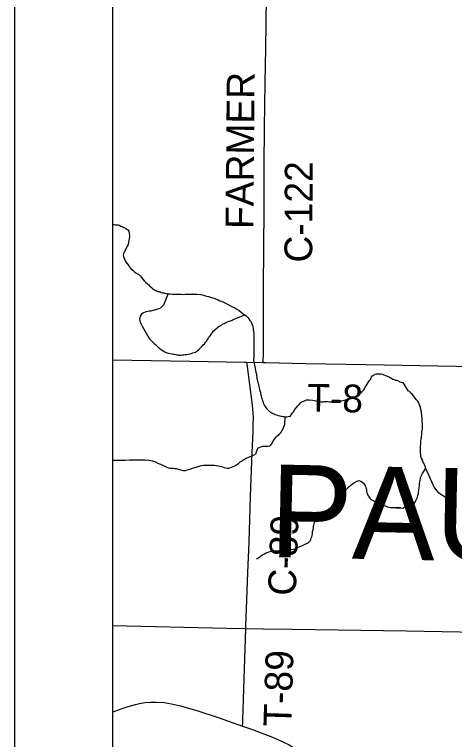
# Model space of a CAD drawing. Extents: x 2.1 to 73.9, y 4 to 26.
# Drawn here: x 41.859 to 42.308, y 21.52 to 22.261 of the extents above; entities that cross this region are included whole.
import ezdxf

# ---------------------------------------------------------------- set-up
doc = ezdxf.new("R2010")
doc.units = 0
for name, color, linetype in [('GM_X_County_Road', 7, 'Continuous'), ('GM_X_County_Road_Text', 7, 'Continuous'), ('GM_X_County_Text', 7, 'Continuous'), ('GM_X_Minor_River', 7, 'Continuous'), ('GM_X_Township_Road', 7, 'Continuous'), ('GM_X_Township_Road_Text', 7, 'Continuous'), ('SH_Data', 7, 'Continuous')]:
    doc.layers.add(name, color=color, linetype=linetype)

msp = doc.modelspace()

# ---------------------------------------------------------------- linework, layer by layer
at = {"layer": 'GM_X_County_Road'}
for points in [[(42.11267, 21.90506), (42.11274, 21.91552), (42.11287, 21.92921), (42.11306, 21.99168), (42.11314, 22.01188), (42.11339, 22.03675), (42.11342, 22.04701), (42.11352, 22.06939), (42.11355, 22.08244), (42.11375, 22.10636), (42.11409, 22.1449), (42.11475, 22.19121), (42.11514, 22.22634), (42.1155, 22.2512), (42.11674, 22.33884), (42.11734, 22.38514), (42.11768, 22.40528)], [(42.09471, 21.63337), (42.09482, 21.63621), (42.09551, 21.65327), (42.09685, 21.69051), (42.0981, 21.72152), (42.0997, 21.76807), (42.10129, 21.81306), (42.10221, 21.83477), (42.10241, 21.84252), (42.10252, 21.84872), (42.10243, 21.85337), (42.10214, 21.85781), (42.10127, 21.86417), (42.09652, 21.90111), (42.09598, 21.90535)], [(41.95853, 21.63624), (42.07549, 21.63377), (42.09471, 21.63337)], [(42.09471, 21.63337), (42.1128, 21.63298), (42.14235, 21.63277), (42.25895, 21.63095), (42.31336, 21.62998), (42.38021, 21.62891), (42.48593, 21.62681), (42.52323, 21.62609), (42.54808, 21.62566), (42.56206, 21.62541), (42.57761, 21.62528), (42.59159, 21.62515), (42.60148, 21.62491)]]:
    msp.add_lwpolyline(points, dxfattribs=at)
at = {"layer": 'GM_X_Minor_River'}
for points in [[(41.95853, 22.04616), (41.96031, 22.0461), (41.96182, 22.04586), (41.96315, 22.04582), (41.96429, 22.04579), (41.96542, 22.04537), (41.96729, 22.04455), (41.9686, 22.04394), (41.97029, 22.04313), (41.97179, 22.04251), (41.97328, 22.04152), (41.97421, 22.04073), (41.97531, 22.03936), (41.97565, 22.03821), (41.97579, 22.03669), (41.97594, 22.03536), (41.97589, 22.03365), (41.97583, 22.03175), (41.97539, 22.02986), (41.97495, 22.02798), (41.9745, 22.02571), (41.97349, 22.02384), (41.97266, 22.02159), (41.97126, 22.01936), (41.97064, 22.01767), (41.97002, 22.01617), (41.96959, 22.01466), (41.96974, 22.01333), (41.97133, 22.00967), (41.97206, 22.0085), (41.97333, 22.00675), (41.97461, 22.005), (41.9757, 22.00326), (41.97754, 22.0013), (41.97938, 21.99935), (41.98123, 21.99777), (41.9829, 21.99639), (41.98459, 21.99577), (41.98552, 21.99498), (41.98644, 21.99419), (41.98736, 21.99321), (41.98827, 21.99185), (41.98955, 21.99029), (41.99102, 21.98854), (41.99268, 21.98696), (41.99417, 21.98578), (41.99564, 21.9844), (41.99693, 21.98303), (41.9986, 21.98165), (41.99989, 21.98047), (42.00138, 21.97947), (42.0027, 21.97886), (42.00382, 21.97845), (42.00494, 21.97784), (42.00627, 21.97761), (42.00721, 21.9772), (42.00833, 21.97679), (42.00965, 21.97637), (42.01117, 21.97632), (42.01305, 21.97569), (42.01609, 21.97541), (42.01798, 21.97516), (42.01987, 21.97491), (42.02178, 21.97504), (42.02406, 21.97497), (42.02653, 21.97489), (42.02881, 21.97482), (42.0309, 21.97475), (42.03318, 21.97487), (42.03546, 21.9748), (42.03794, 21.97491), (42.04079, 21.97501), (42.04231, 21.97496), (42.04346, 21.97512), (42.04479, 21.97508), (42.04896, 21.97457), (42.05065, 21.97413), (42.05273, 21.97369), (42.0548, 21.97305), (42.05688, 21.97242), (42.05876, 21.97179), (42.06064, 21.97116), (42.06234, 21.97073), (42.0644, 21.9699), (42.06666, 21.96907), (42.06815, 21.96827), (42.06985, 21.96764), (42.07135, 21.96703), (42.07266, 21.96642), (42.07397, 21.96581), (42.07547, 21.965), (42.07678, 21.96439), (42.07902, 21.96318), (42.08127, 21.96216), (42.08352, 21.96114), (42.08576, 21.95955), (42.08799, 21.95815), (42.09022, 21.95656), (42.09227, 21.95498), (42.09394, 21.95378)], [(42.01538, 21.97547), (42.01058, 21.96361), (42.0098, 21.96269), (42.00863, 21.96177), (42.00764, 21.96066), (42.00591, 21.95996), (42.00457, 21.95962), (42.00264, 21.95892), (42.00149, 21.95858), (41.99996, 21.95825), (41.99881, 21.95809), (41.99785, 21.95774), (41.99614, 21.95761), (41.99441, 21.95709), (41.99269, 21.95676), (41.9898, 21.95571), (41.98824, 21.95443), (41.98745, 21.95351), (41.98685, 21.95258), (41.98642, 21.95088), (41.98638, 21.94974), (41.98653, 21.94841), (41.98668, 21.94726), (41.98722, 21.94611), (41.98792, 21.94438), (41.989, 21.94225), (41.99025, 21.93975), (41.9917, 21.93742), (41.99315, 21.9351), (41.9944, 21.93259), (41.99567, 21.93046), (41.99676, 21.9289), (41.99805, 21.92753), (41.99934, 21.92635), (42.00119, 21.92459), (42.00248, 21.92341), (42.00377, 21.92204), (42.00525, 21.92066), (42.00711, 21.91946), (42.00859, 21.91809), (42.01026, 21.91689), (42.01194, 21.91589), (42.01344, 21.91528), (42.01457, 21.91486), (42.0159, 21.91463), (42.01759, 21.9142), (42.01968, 21.91394), (42.021, 21.91371), (42.02214, 21.91348), (42.02327, 21.91326), (42.0244, 21.91303), (42.02573, 21.9128), (42.02687, 21.91277), (42.02839, 21.91272), (42.02991, 21.91286), (42.03144, 21.913), (42.03296, 21.91315), (42.03468, 21.91347), (42.03622, 21.9138), (42.03775, 21.91414), (42.03889, 21.91429), (42.04063, 21.915), (42.04332, 21.91586), (42.04506, 21.91695), (42.04662, 21.91823), (42.0476, 21.91896), (42.04897, 21.92043), (42.04976, 21.92136), (42.05134, 21.92302), (42.05252, 21.92431), (42.05371, 21.92598), (42.0547, 21.92709), (42.0553, 21.92802), (42.05609, 21.92914), (42.05669, 21.93007), (42.05789, 21.93193), (42.05868, 21.93285), (42.05928, 21.93378), (42.05988, 21.93472), (42.06067, 21.93564), (42.06187, 21.9375), (42.06323, 21.93841), (42.06402, 21.93934), (42.06519, 21.94025), (42.06635, 21.94116), (42.06733, 21.94189), (42.06849, 21.94261), (42.06985, 21.94333), (42.07102, 21.94425), (42.07275, 21.94514), (42.07449, 21.94584), (42.07603, 21.94656), (42.07795, 21.94726), (42.07911, 21.94779), (42.08007, 21.94814), (42.08104, 21.94849), (42.082, 21.94903), (42.08296, 21.94938), (42.09394, 21.95378)], [(42.09394, 21.95378), (42.09561, 21.9524), (42.0969, 21.95122), (42.098, 21.94986), (42.0989, 21.94812), (42.10018, 21.94656), (42.10088, 21.94464), (42.10159, 21.94291), (42.10212, 21.94156), (42.10226, 21.94004), (42.1024, 21.93851), (42.10273, 21.93679), (42.10287, 21.93527), (42.10301, 21.93356), (42.10295, 21.93166), (42.10287, 21.92938), (42.10317, 21.92671), (42.10308, 21.92368), (42.10298, 21.92045), (42.10287, 21.91703), (42.10295, 21.91361), (42.10286, 21.91058), (42.10257, 21.90755), (42.10399, 21.90054)], [(42.10399, 21.90054), (42.105, 21.89511), (42.10568, 21.89318), (42.10582, 21.89185), (42.10594, 21.89013), (42.10626, 21.8886), (42.1066, 21.88763), (42.10693, 21.88629), (42.10726, 21.88514), (42.10758, 21.88361), (42.10791, 21.88226), (42.10823, 21.88092), (42.10886, 21.87748), (42.1092, 21.87651), (42.10935, 21.87555), (42.10969, 21.87459), (42.10984, 21.87345), (42.11017, 21.87229), (42.11051, 21.87133), (42.11067, 21.87037), (42.11116, 21.86845), (42.11168, 21.8671), (42.11219, 21.86556), (42.11269, 21.86383), (42.11321, 21.86267), (42.11374, 21.8617), (42.11463, 21.86014), (42.11535, 21.85898), (42.11607, 21.858), (42.11735, 21.8568), (42.11827, 21.85582), (42.11919, 21.85521), (42.1203, 21.8544), (42.12142, 21.85379), (42.12254, 21.85318), (42.12366, 21.85275), (42.12459, 21.85214), (42.12609, 21.8517), (42.12797, 21.85106), (42.12967, 21.85061), (42.1308, 21.85037), (42.13174, 21.85014), (42.13307, 21.8499), (42.13401, 21.84986), (42.13534, 21.84962), (42.13667, 21.84975), (42.1382, 21.84988), (42.13936, 21.85021), (42.14032, 21.85037), (42.14133, 21.85185), (42.14254, 21.8537), (42.14374, 21.85517), (42.14456, 21.85665), (42.14797, 21.86089), (42.14957, 21.86272), (42.15057, 21.86401), (42.15154, 21.86454), (42.15271, 21.86525), (42.15368, 21.86578), (42.15465, 21.86612), (42.156, 21.86664), (42.15697, 21.86698), (42.15792, 21.86694), (42.15963, 21.86687), (42.16323, 21.86654), (42.16493, 21.86628), (42.16626, 21.86603), (42.16815, 21.86577), (42.16948, 21.86571), (42.17041, 21.8653), (42.17193, 21.86505), (42.17288, 21.86501), (42.17402, 21.86496), (42.17497, 21.86511), (42.17612, 21.86526), (42.17727, 21.8654), (42.1786, 21.86535), (42.18049, 21.86508), (42.1822, 21.86501), (42.18467, 21.86491), (42.1883, 21.86514), (42.1904, 21.86544), (42.19175, 21.86576), (42.19271, 21.8661), (42.19406, 21.86643), (42.1954, 21.86676), (42.19656, 21.86709), (42.19771, 21.86742), (42.19868, 21.86776), (42.20021, 21.86808), (42.20176, 21.86878), (42.20658, 21.87029), (42.20755, 21.87063), (42.20929, 21.87132), (42.21026, 21.87185), (42.21144, 21.87276), (42.21244, 21.87386), (42.21364, 21.87533)], [(42.21364, 21.87533), (42.21543, 21.87734), (42.21604, 21.87827), (42.21686, 21.87976), (42.21769, 21.88143), (42.21871, 21.8831), (42.21973, 21.88477), (42.22093, 21.88624), (42.22213, 21.88771), (42.22255, 21.88864), (42.22318, 21.89014), (42.22437, 21.89142), (42.22555, 21.89232), (42.22653, 21.89304), (42.22788, 21.89356), (42.22922, 21.89369), (42.23017, 21.89366), (42.23207, 21.89358), (42.23302, 21.89354), (42.23452, 21.8931), (42.23583, 21.89248), (42.23752, 21.89184), (42.23883, 21.89141), (42.23995, 21.89079), (42.24127, 21.89036), (42.2422, 21.88994), (42.24387, 21.88892), (42.24498, 21.88812), (42.24649, 21.88768), (42.2478, 21.88724), (42.24874, 21.88702), (42.24987, 21.88659), (42.25229, 21.88535), (42.25361, 21.88492), (42.25436, 21.8847), (42.25575, 21.8846)], [(42.27405, 21.80745), (42.27324, 21.81348), (42.27332, 21.81614), (42.27342, 21.81975), (42.27367, 21.82183), (42.27372, 21.82354), (42.27377, 21.82506), (42.274, 21.82658), (42.27424, 21.82828), (42.27447, 21.82979), (42.27451, 21.83112), (42.27475, 21.83264), (42.27479, 21.83416), (42.27503, 21.83586), (42.27526, 21.83718), (42.27531, 21.8387), (42.27534, 21.84003), (42.27537, 21.84098), (42.27521, 21.84213), (42.2751, 21.84479), (42.27514, 21.84612), (42.27483, 21.8486), (42.27469, 21.85032), (42.27455, 21.85203), (42.2744, 21.85337), (42.27424, 21.85432), (42.27408, 21.85547), (42.27392, 21.85642), (42.27376, 21.85738), (42.27341, 21.85834), (42.27325, 21.85967), (42.27272, 21.86102), (42.27218, 21.86199), (42.27183, 21.86295), (42.2713, 21.86448), (42.27058, 21.86564), (42.26909, 21.86702), (42.268, 21.86876), (42.26727, 21.86973), (42.26616, 21.87091), (42.26469, 21.87266), (42.26322, 21.87422), (42.2623, 21.87539), (42.26118, 21.87599), (42.26025, 21.87678), (42.25575, 21.8846)], [(42.13476, 21.84959), (42.13444, 21.84148), (42.13235, 21.83682), (42.13173, 21.83552), (42.13091, 21.83422), (42.12991, 21.83293), (42.12853, 21.83166), (42.12772, 21.83055), (42.12654, 21.82965), (42.12495, 21.828), (42.12376, 21.82672), (42.12315, 21.82579), (42.12254, 21.82468), (42.12212, 21.82375), (42.12151, 21.82282), (42.1201, 21.82079), (42.11891, 21.8197), (42.11719, 21.81939), (42.11528, 21.81927), (42.11319, 21.81936), (42.11204, 21.81921), (42.11108, 21.81906), (42.10993, 21.81873), (42.10819, 21.81804), (42.10664, 21.81734), (42.10466, 21.81151)], [(42.02822, 21.79546), (42.02936, 21.79505), (42.03069, 21.79483), (42.03163, 21.79462), (42.03335, 21.79477), (42.03489, 21.79531), (42.03796, 21.79619), (42.04045, 21.79708), (42.04314, 21.79797), (42.04506, 21.7985), (42.04602, 21.79886), (42.04717, 21.79921), (42.04813, 21.79957), (42.04966, 21.79973), (42.05176, 21.80006), (42.05367, 21.8002), (42.05501, 21.80017), (42.05672, 21.80013), (42.05787, 21.8003), (42.05901, 21.80027), (42.06091, 21.80023), (42.06301, 21.80018), (42.06472, 21.79995), (42.06642, 21.79953), (42.06813, 21.7993), (42.06984, 21.79888), (42.07097, 21.79848), (42.07267, 21.79768), (42.07571, 21.79723), (42.07723, 21.7972), (42.07857, 21.79754), (42.08011, 21.79808), (42.08203, 21.7988), (42.08376, 21.79952), (42.08569, 21.8008), (42.08744, 21.80209), (42.08919, 21.80358), (42.09092, 21.8043), (42.09189, 21.80523), (42.09305, 21.80596), (42.09421, 21.80669), (42.09537, 21.80724), (42.10466, 21.81151)], [(41.95853, 21.80517), (41.95985, 21.80519), (41.96385, 21.80529), (41.96786, 21.80539), (41.97167, 21.8055), (41.97587, 21.80559), (41.98044, 21.80568), (41.98463, 21.80577), (41.98863, 21.80568), (41.99206, 21.8056), (41.99567, 21.80533), (41.99777, 21.80509), (41.99947, 21.80467), (42.00061, 21.80446), (42.00174, 21.80386), (42.0057, 21.80206), (42.00759, 21.80125), (42.0091, 21.80065), (42.01079, 21.79985), (42.01211, 21.79906), (42.01343, 21.79846), (42.01475, 21.79786), (42.01569, 21.79746), (42.01721, 21.79723), (42.01855, 21.7972), (42.02083, 21.79715), (42.02235, 21.79693), (42.02368, 21.7969), (42.02482, 21.79649), (42.02633, 21.79607), (42.02728, 21.79586), (42.02822, 21.79546)], [(42.25284, 21.75671), (42.25538, 21.75619), (42.25807, 21.75784), (42.26075, 21.75854), (42.26266, 21.75907), (42.264, 21.75942), (42.26515, 21.75958), (42.26593, 21.76071), (42.2671, 21.76182), (42.26807, 21.76294), (42.26887, 21.76463), (42.26967, 21.76632), (42.27027, 21.76764), (42.27069, 21.76934), (42.2711, 21.77085), (42.27134, 21.77274), (42.27156, 21.77407), (42.27158, 21.7754), (42.27181, 21.77691), (42.27183, 21.77786), (42.27224, 21.77899), (42.27229, 21.78146), (42.2727, 21.78278), (42.27272, 21.78373), (42.27294, 21.78505), (42.27316, 21.78619), (42.27338, 21.78751), (42.27458, 21.79034), (42.27538, 21.79184), (42.27636, 21.79334), (42.27695, 21.79427), (42.27774, 21.79558), (42.27854, 21.79709), (42.27837, 21.79823), (42.27821, 21.79937), (42.27748, 21.80072), (42.27656, 21.80226), (42.27583, 21.80379), (42.27529, 21.80476), (42.27428, 21.80745), (42.27529, 21.80476)], [(42.27853, 21.79708), (42.28577, 21.7804), (42.28631, 21.77943), (42.28705, 21.77809), (42.28777, 21.77674), (42.2887, 21.77577), (42.28981, 21.77404), (42.29092, 21.77268), (42.29279, 21.77169), (42.29391, 21.77072), (42.29503, 21.76974), (42.29672, 21.76875), (42.29841, 21.76796), (42.30575, 21.76456), (42.30877, 21.76354)], [(42.10618, 21.70433), (42.10657, 21.70489), (42.10773, 21.70563), (42.10909, 21.70655), (42.11025, 21.70747), (42.1118, 21.70858), (42.11392, 21.70948), (42.11566, 21.71058), (42.11777, 21.71148), (42.11988, 21.712), (42.12198, 21.71234), (42.12389, 21.71248), (42.12523, 21.71264), (42.12695, 21.71279), (42.12924, 21.71293), (42.1321, 21.71325), (42.13516, 21.71356), (42.1384, 21.71386), (42.14107, 21.71399), (42.14337, 21.71432), (42.1451, 21.71485), (42.1474, 21.71575), (42.15048, 21.7172), (42.15356, 21.71846), (42.15607, 21.71973), (42.15838, 21.72082), (42.15955, 21.72194), (42.16052, 21.72286), (42.16131, 21.72418), (42.16172, 21.7255), (42.16214, 21.72701), (42.16255, 21.72852), (42.16279, 21.73042), (42.16302, 21.73231), (42.16386, 21.73552), (42.16388, 21.73648), (42.1641, 21.7378), (42.16432, 21.73894), (42.16473, 21.74026), (42.16495, 21.74158), (42.16535, 21.74272), (42.16576, 21.74366), (42.16616, 21.74479), (42.16695, 21.7461), (42.16813, 21.74759), (42.16892, 21.74872), (42.16989, 21.74927), (42.17085, 21.75), (42.17201, 21.75074), (42.17336, 21.75147), (42.1751, 21.75238), (42.17683, 21.7531), (42.17896, 21.75457), (42.18166, 21.75584), (42.18339, 21.75656), (42.18474, 21.75748), (42.18611, 21.75878), (42.18786, 21.76045), (42.18943, 21.76251), (42.191, 21.76456), (42.19219, 21.76682), (42.19378, 21.76944), (42.19496, 21.77132), (42.19575, 21.77244), (42.19636, 21.77395), (42.19695, 21.77488), (42.19793, 21.77619), (42.1989, 21.77693), (42.20046, 21.77842), (42.20143, 21.77915), (42.2024, 21.78008), (42.20376, 21.78119), (42.20492, 21.78193), (42.20589, 21.78247), (42.20724, 21.7832), (42.20936, 21.7843), (42.21032, 21.78465), (42.21126, 21.78425), (42.21221, 21.78385), (42.21371, 21.78287), (42.21521, 21.78169), (42.21576, 21.78073), (42.2165, 21.77976), (42.21704, 21.77861), (42.21759, 21.77746), (42.21794, 21.77631), (42.2181, 21.77497), (42.21826, 21.77364), (42.21842, 21.7723), (42.21877, 21.77096), (42.21932, 21.76981), (42.21987, 21.76885), (42.22079, 21.7675), (42.2219, 21.76614), (42.22321, 21.76478), (42.22471, 21.76398), (42.22584, 21.76339), (42.22698, 21.76298), (42.2283, 21.76257), (42.22981, 21.76197), (42.23151, 21.76117)], [(42.23151, 21.76117), (42.2332, 21.76018), (42.23566, 21.75936), (42.23735, 21.75856), (42.23943, 21.75776), (42.24133, 21.75733), (42.24266, 21.75711), (42.2438, 21.7569), (42.24475, 21.75687), (42.24589, 21.75685), (42.24703, 21.75682), (42.24798, 21.75661), (42.25284, 21.75671), (42.24798, 21.75661)]]:
    msp.add_lwpolyline(points, dxfattribs=at)
at = {"layer": 'GM_X_Township_Road'}
msp.add_line((42.09598, 21.90535), (42.11267, 21.90506), dxfattribs=at)
for points in [[(41.95853, 21.90797), (42.03757, 21.90651), (42.09352, 21.90539), (42.09598, 21.90535)], [(42.11267, 21.90506), (42.11528, 21.90501), (42.1557, 21.90414), (42.21788, 21.90323), (42.29093, 21.90169), (42.34689, 21.90062), (42.38575, 21.89981), (42.4184, 21.89925), (42.46814, 21.89831), (42.53498, 21.89697), (42.56451, 21.89647), (42.59249, 21.89612), (42.61136, 21.89583)], [(42.09157, 21.53364), (42.0917, 21.53679), (42.09184, 21.54048), (42.09255, 21.56073), (42.09471, 21.63337)], [(41.95853, 21.54789), (41.96273, 21.54959), (41.97448, 21.55367), (41.98197, 21.55572), (41.98629, 21.55672), (41.99172, 21.55763), (41.99732, 21.55805), (42.00353, 21.55818), (42.01128, 21.55762), (42.01896, 21.55644), (42.02804, 21.55434), (42.04594, 21.54916), (42.0666, 21.54234), (42.09157, 21.53364)], [(42.09157, 21.53364), (42.10182, 21.53006), (42.12216, 21.52234), (42.1321, 21.51793), (42.13899, 21.51434), (42.14557, 21.51021), (42.15301, 21.50459), (42.16119, 21.49743), (42.18385, 21.47615), (42.18812, 21.47163), (42.19195, 21.46674), (42.19604, 21.46014), (42.20643, 21.44102), (42.20972, 21.43399), (42.21177, 21.42812), (42.21373, 21.4206), (42.21519, 21.41297), (42.21603, 21.40525), (42.21616, 21.39904), (42.21595, 21.38972), (42.21604, 21.38817), (42.21636, 21.38665), (42.21694, 21.38521), (42.21732, 21.3846)]]:
    msp.add_lwpolyline(points, dxfattribs=at)
at = {"layer": 'SH_Data'}
for p, q in [((41.85853, 25.00511), (41.85853, 18.00511)), ((41.95853, 24.90511), (41.95853, 18.10511))]:
    msp.add_line(p, q, dxfattribs=at)

# ---------------------------------------------------------------- texts
at = {"layer": 'GM_X_County_Road_Text'}
for s, rotation, p in [('FARMER', 89.5004, (42.10248, 22.04148)), ('C-122', 89.7243, (42.16266, 22.00722)), ('C-89', 87.94594, (42.14583, 21.66642))]:
    msp.add_text(s, height=0.028409, rotation=rotation, dxfattribs=at).set_placement(p)
at = {"layer": 'GM_X_County_Text'}
msp.add_text('PAULDING COUNTY', height=0.094697, rotation=358.83177, dxfattribs=at).set_placement((42.1185, 21.70637))
at = {"layer": 'GM_X_Township_Road_Text'}
for s, rotation, p in [('T-8', 359.04568, (42.15734, 21.85495)), ('T-89', 88.23177, (42.14119, 21.53271))]:
    msp.add_text(s, height=0.028409, rotation=rotation, dxfattribs=at).set_placement(p)

doc.saveas('drawing.dxf')
